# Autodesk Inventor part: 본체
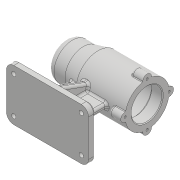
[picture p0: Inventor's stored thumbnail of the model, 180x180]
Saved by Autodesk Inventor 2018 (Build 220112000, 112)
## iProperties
Created: 2019-07
Part Number: 본체
Material: 일반
Document SubType Name: Modeling
Designer: USER
Density: 1 g/cm^3
Appearance: 기본값
Author: USER
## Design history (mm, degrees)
sketch "스케치1"
  geometry: L1 (-46, 35)-(46, 35); L2 (56, 25)-(56, -25); L3 (46, -35)-(-46, -35); L4 (-56, -25)-(-56, 25); L5 (-56, 35)-(56, -35); L6 (56, 35)-(-56, -35); A1 r 10 centre (46, 25) between (56, 25) and (46, 35); A2 r 10 centre (-46, 25) between (-46, 35) and (-56, 25); A3 r 10 centre (-46, -25) between (-56, -25) and (-46, -35); A4 r 10 centre (46, -25) between (46, -35) and (56, -25); 1 further point
  constraints: 12 end point, 8 point on circle, 8 point on line, 8 tangent, 4 centre point, 3 equal radius, 2 midpoint, 2 parallel, 1 horizontal, 1 perpendicular
  dimensions: "d0" = 70 distance of L6.start L5.end; "d1" = 112 distance of L5.start L6.start; "d2" = 10 radius of A1
extrude "돌출1" new body sketch "스케치1" distance "d3" = 10; taper "d4" = 0 deg
sketch "스케치2"
  geometry: L1 (-46, -25)-(46, -25); L2 (46, -25)-(46, 25); L3 (46, 25)-(-46, 25); L4 (-46, 25)-(-46, -25); L5 (-46, -25)-(46, 25); L6 (46, -25)-(-46, 25); L7 (0, 35)-(0, -35); L8 (-56, 0)-(56, 0); C1 r 3 at (-46, 25); C2 r 3 at (46, 25); C3 r 3 at (-46, -25); C4 r 3 at (46, -25); 1 further point
  constraints: 16 end point, 4 centre point, 3 symmetric about line, 2 midpoint, 2 parallel, 1 coincident, 1 horizontal, 1 perpendicular, 3 other
  dimensions: "d5" = 92 distance of L2.end L3.end; "d6" = 50 distance of L1.end L2.end; "d7" = 6 diameter of C1
extrude "돌출2" cut sketch "스케치2" distance "d8" = 10; taper "d9" = 0 deg
chamfer "모따기1" distance "d10" = 3; stored, may be unused: second distance "d11" = 2, angle "d12" = 45 deg
sketch "스케치3"
  geometry: L1 (-56, 80)-(56, 80); L2 (-46, 0)-(46, 0) reference; L3 (56, 0)-(56, 7) reference; L4 (-56, 0)-(-56, 7) reference; L5 (56, 110)-(-11, 110); L6 (-11, 110)-(-31, 105); L7 (-31, 105)-(-46, 105); L8 (-56, 95)-(-56, 80); L9 (-47, 90.5)-(-47, 95.7); L10 (-46.7, 96)-(-43, 96); L11 (-43, 96)-(-43, 97.2); L12 (-42.7, 97.5)-(-25, 97.5); L13 (-25, 97.5)-(-25, 100.7); L14 (56, 110)-(56, 101); L15 (56, 101)-(41, 101); L16 (41, 101)-(41, 101); L17 (38, 104)-(-10, 104); L18 (-13, 101)-(-13, 101); L19 (-24.7, 101)-(-13, 101); L20 (-56, 80)-(-50, 80); L21 (-50, 80)-(-50, 87.5); L22 (-47, 90.5)-(-47, 90.5); A1 r 0.3 centre (-46.7, 95.7) between (-46.7, 96) and (-47, 95.7); A2 r 0.3 centre (-42.7, 97.2) between (-42.7, 97.5) and (-43, 97.2); A3 r 0.3 centre (-24.7, 100.7) between (-24.7, 101) and (-25, 100.7); A4 r 10 centre (-46, 95) between (-46, 105) and (-56, 95); A5 r 3 centre (-47, 87.5) between (-47, 90.5) and (-50, 87.5); A6 r 3 centre (-10, 101) between (-10, 104) and (-13, 101); A7 r 3 centre (38, 101) between (41, 101) and (38, 104); 1 further point
  constraints: 38 end point, 14 point on circle, 14 tangent, 7 centre point, 7 perpendicular, 5 point on line, 4 horizontal, 4 vertical, 3 equal radius, 1 parallel
  dimensions: "d13" = 80 distance between parallel lines of L2 L1; "d14" = 60 diameter of L5 L1; "d15" = 50 diameter of L7 L1; "d16" = 112 distance from line of L8 L5.start; "d17" = 45 distance from line of L8 L5.end; "d18" = 25 distance from line of L8 L6.end; "d19" = 42 diameter of L15 L1; "d20" = 48 diameter of L17 L1; "d21" = 15 distance of L14.end L15.end; "d22" = 54 distance between parallel lines of L16 L18; "d23" = 12 distance between parallel lines of L18 L13; "d24" = 18 distance between parallel lines of L11 L13; "d25" = 4 distance between parallel lines of L9 L11; "d26" = 3 distance between parallel lines of L9 L21; "d27" = 21 diameter of L22 L1; "d28" = 32 diameter of L10 L1; "d29" = 35 diameter of L12 L1; "d30" = 0.3 radius of A1; "d31" = 0.3 radius of A2 (derived); "d32" = 10 radius of A4 (derived); "d33" = 3 radius of A5; "d34" = 42 diameter of L19 L1
revolve "회전1" sketch "스케치3" stored, may be unused: angle "d35" = 90 deg
chamfer "모따기2" distance "d36" = 1; stored, may be unused: second distance "d37" = 2, angle "d38" = 45 deg
sketch "스케치5"
  geometry: L1 (0, 0)-(53, 0); L2 (0, 0)-(0, 32); L3 (-46, 32)-(46, 32) reference; L4 (53, 25)-(53, -25) reference; L5 (56, -25)-(56, 25) reference; L6 (0, -4)-(31, -4); L7 (31, -4)-(31, 4); L8 (31, 4)-(0, 4); L9 (0, 4)-(0, -4); L10 (0, -4)-(31, 4); L11 (31, -4)-(0, 4); 1 further point
  constraints: 16 end point, 4 midpoint, 2 horizontal, 2 parallel, 1 collinear, 1 perpendicular, 1 point on line, 1 vertical
  dimensions: "d41" = 8 distance between parallel lines of L6 L8; "d42" = 25 distance between parallel lines of L5 L7
extrude "돌출3" join sketch "스케치5" stored distance "d43" = 10; taper "d44" = 0 deg
sketch "스케치6"
  geometry: L1 (-46, 10)-(46, 10) reference; L2 (-36, 10)-(-20.57, 52.393); L3 (-56, 0)-(-56, 7) reference; L4 (-56, 65)-(-56, 95) reference; L5 (-46, 105)-(-31, 105) reference; L6 (-31, 105)-(-11, 110) reference; L7 (-11, 110)-(56, 110) reference; L8 (56, 110)-(56, 102) reference; L9 (56, 102)-(55, 101) reference; L10 (55, 101)-(41, 101) reference; L11 (38, 104)-(-10, 104) reference; L12 (-13, 101)-(-24.7, 101) reference; L13 (-25, 100.7)-(-25, 97.5) reference; L14 (-25, 97.5)-(-42.7, 97.5) reference; L15 (-43, 97.2)-(-43, 96) reference; L16 (-43, 96)-(-46.7, 96) reference; L17 (-47, 95.7)-(-47, 90.5) reference; L18 (-50, 87.5)-(-50, 72.5) reference; L19 (-47, 69.5)-(-47, 64.3) reference; L20 (-46.7, 64)-(-43, 64) reference; L21 (-43, 64)-(-43, 62.8) reference; L22 (-42.7, 62.5)-(-25, 62.5) reference; L23 (-25, 62.5)-(-25, 59.3) reference; L24 (-24.7, 59)-(-13, 59) reference; L25 (-10, 56)-(38, 56) reference; L26 (41, 59)-(55, 59) reference; L27 (55, 59)-(56, 58) reference; L28 (56, 58)-(56, 50) reference; L29 (56, 50)-(31, 50) reference; L30 (31, 50)-(31, 10) reference; L31 (31, 10)-(53, 10) reference; L32 (53, 10)-(56, 7) reference; L33 (56, 7)-(56, 0) reference; L34 (56, 0)-(-56, 0) reference; L35 (-56, 0)-(-56, 7) reference; L36 (-56, 7)-(-53, 10) reference; L37 (-53, 10)-(0, 10) reference; L38 (0, 10)-(0, 50) reference; L39 (0, 50)-(-11, 50) reference; L40 (-11, 50)-(-31, 55) reference; L41 (-31, 55)-(-46, 55) reference; A1 r 10 centre (-46, 95) between (-46, 105) and (-56, 95) reference; A2 r 3 centre (38, 101) between (41, 101) and (38, 104) reference; A3 r 3 centre (-10, 101) between (-10, 104) and (-13, 101) reference; A4 r 0.3 centre (-24.7, 100.7) between (-24.7, 101) and (-25, 100.7) reference; A5 r 0.3 centre (-42.7, 97.2) between (-42.7, 97.5) and (-43, 97.2) reference; A6 r 0.3 centre (-46.7, 95.7) between (-46.7, 96) and (-47, 95.7) reference; A7 r 3 centre (-47, 87.5) between (-47, 90.5) and (-50, 87.5) reference; A8 r 3 centre (-47, 72.5) between (-50, 72.5) and (-47, 69.5) reference; A9 r 0.3 centre (-46.7, 64.3) between (-47, 64.3) and (-46.7, 64) reference; A10 r 0.3 centre (-42.7, 62.8) between (-43, 62.8) and (-42.7, 62.5) reference; A11 r 0.3 centre (-24.7, 59.3) between (-25, 59.3) and (-24.7, 59) reference; A12 r 3 centre (-10, 59) between (-13, 59) and (-10, 56) reference; A13 r 3 centre (38, 59) between (38, 56) and (41, 59) reference; A14 r 10 centre (-46, 65) between (-56, 65) and (-46, 55) reference; 1 further point
  constraints: 2 end point, 2 point on line
  dimensions: "d45" = 20 distance from line of L3 L2.start; "d46" = 110 deg angle of L1 L2
feature "리브1" sketch "스케치6" dims "d47" = 1, "d48" = 8, "d49" = 0, "d50" = 0, "d51" = 1, "d52" = 1
sketch "스케치7"
  geometry: L1 (10, 25)-(10, -25) reference; L2 (10, 28)-(52.708, 12.456); L3 (0, 0)-(80, 0); L4 (0, 35)-(7, 35) reference; 1 further point
  constraints: 4 end point, 1 coincident, 1 horizontal, 1 point on line, 2 other
  dimensions: "d53" = 7 distance from line of L4 L2.start; "d54" = 110 deg angle of L1 L2
feature "리브2" sketch "스케치7" dims "d55" = 1, "d56" = 8, "d57" = 0, "d58" = 0, "d59" = 1, "d60" = 1
fillet "모깎기1" dims "d61" = 3
sketch "스케치9"
  geometry: L1 (0, 0)-(0, 30); C1 r 6 at (0, 30); 1 further point
  constraints: 2 end point, 1 centre point, 1 vertical, 1 vertical alignment, 1 other
  dimensions: "d68" = 12 diameter of C1
extrude "돌출4" join sketch "스케치9" distance "d69" = 16; taper "d70" = 0 deg
fillet "모깎기2" dims "d71" = 3
fillet "모깎기3" dims "d72" = 1
sketch "스케치11"
  geometry: A1 r 30 centre (0, -30) between (2.779, -0.129) and (-2.779, -0.129) reference; 2 further points
  constraints: 1 point on circle
hole "구멍1" sketch "스케치11" at (0, 0) diameter "d73" = 3.242; stored, may be unused: countersink angle "d77" = 90 deg, drill point angle "d79" = 118 deg; dims "d74" = 8, "d75" = 4, "d76" = 2, "d78" = 11
node "솔리드1"
mirror "미러1"
pattern_circular "원형 패턴1" dims "d81" = 360 deg
node "절단 모서리 투영1"
